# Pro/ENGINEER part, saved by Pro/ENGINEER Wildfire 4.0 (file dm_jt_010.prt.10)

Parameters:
  METRIC = "NO"

Other parameters: PITCH, DRILL_POINT_ANGLE, DRILL_DEPTH, DRILL_DIAMETER, THREAD_DIAMETER, THREADS_PER_INCH, THREAD_DEPTH, THREAD_LENGTH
